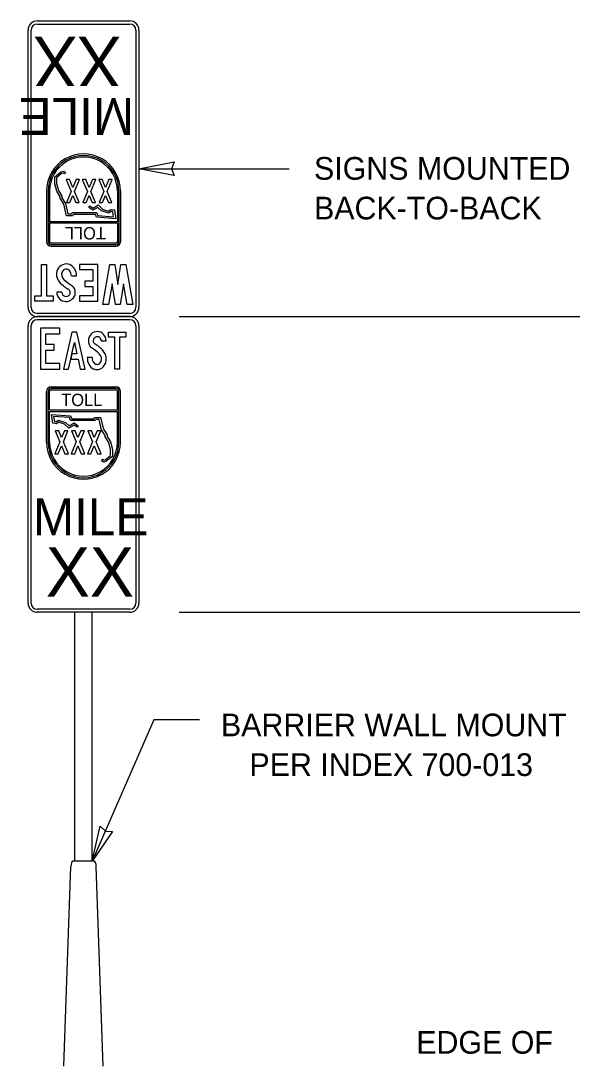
# Model space of a CAD drawing. Extents: x 57428 to 58066, y 11696 to 12105.
# Drawn here: x 57752.3 to 57820.2, y 11796.7 to 11925.7 of the extents above; entities that cross this region are included whole.
import ezdxf

# ---------------------------------------------------------------- set-up
doc = ezdxf.new("R2010")
doc.units = 0
for name, color, linetype in [('DimLines_dp', 7, 'Continuous'), ('NonPlottingEle_dp', 7, 'Continuous'), ('SignPanel', 7, 'Continuous'), ('XSGrdLine_ex', 7, 'Continuous')]:
    doc.layers.add(name, color=color, linetype=linetype)

msp = doc.modelspace()

# ---------------------------------------------------------------- linework, layer by layer
at = {"layer": 'DimLines_dp'}
for p, q in [((57766.83, 11907.47), (57771.18, 11908.31)), ((57771.18, 11908.31), (57770.85, 11907.47)), ((57766.83, 11907.47), (57785.36, 11907.47)), ((57771.18, 11906.66), (57766.83, 11907.47)), ((57770.85, 11907.47), (57771.18, 11906.66)), ((57919.19, 11889.21), (57771.8, 11889.21)), ((57919.19, 11852.71), (57771.8, 11852.71)), ((57768.66, 11839.46), (57761.07, 11822.02)), ((57774.31, 11839.46), (57768.66, 11839.46)), ((57761.07, 11822.02), (57762.04, 11826.34)), ((57763.55, 11825.68), (57761.07, 11822.02)), ((57762.04, 11826.34), (57762.68, 11825.7)), ((57762.68, 11825.7), (57763.55, 11825.68))]:
    msp.add_line(p, q, dxfattribs=at)
at = {"layer": 'NonPlottingEle_dp'}
for p, q in [((57758.91, 11822.02), (57758.91, 11852.73)), ((57761.07, 11822.02), (57761.07, 11852.73))]:
    msp.add_line(p, q, dxfattribs=at)
at = {"layer": 'SignPanel'}
for p, q in [((57756.43, 11906.48), (57757.18, 11907.09)), ((57757.29, 11906.88), (57756.66, 11906.37)), ((57757.18, 11907.09), (57757.54, 11907.18)), ((57757.49, 11906.93), (57757.29, 11906.88)), ((57757.63, 11906.83), (57757.49, 11906.93)), ((57757.54, 11907.18), (57757.77, 11907.02)), ((57757.77, 11907.02), (57757.63, 11906.83)), ((57756.43, 11905.62), (57756.43, 11906.48)), ((57756.68, 11904.69), (57756.43, 11905.62)), ((57756.66, 11906.37), (57756.66, 11905.65)), ((57756.66, 11905.65), (57756.9, 11904.78)), ((57755.43, 11904.74), (57755.43, 11898.46)), ((57755.62, 11904.74), (57755.62, 11898.46)), ((57755.81, 11904.74), (57755.81, 11900.94)), ((57757.09, 11904.02), (57756.68, 11904.69)), ((57756.9, 11904.78), (57757.32, 11904.08)), ((57764.17, 11904.74), (57764.17, 11900.94)), ((57764.36, 11904.74), (57764.36, 11898.46)), ((57764.55, 11904.74), (57764.55, 11898.46)), ((57757.09, 11903.83), (57757.09, 11904.02)), ((57757.54, 11903.11), (57757.09, 11903.83)), ((57757.32, 11904.08), (57757.32, 11903.9)), ((57757.32, 11903.9), (57757.76, 11903.2)), ((57757.88, 11901.68), (57757.54, 11903.11)), ((57757.76, 11903.2), (57758.06, 11901.91)), ((57761.16, 11902.62), (57761.79, 11903)), ((57761.79, 11903), (57762.33, 11902.5)), ((57758.61, 11901.68), (57757.88, 11901.68)), ((57758.06, 11901.91), (57758.49, 11901.91)), ((57758.49, 11901.91), (57758.59, 11902.06)), ((57758.59, 11902.06), (57761.6, 11902.06)), ((57758.71, 11901.83), (57758.61, 11901.68)), ((57761.45, 11901.83), (57758.71, 11901.83)), ((57760.65, 11902.69), (57760.78, 11902.88)), ((57761.15, 11902.35), (57760.65, 11902.69)), ((57760.78, 11902.88), (57761.16, 11902.62)), ((57761.76, 11902.71), (57761.15, 11902.35)), ((57761.58, 11901.49), (57761.45, 11901.83)), ((57761.6, 11902.06), (57761.74, 11901.7)), ((57761.74, 11901.7), (57763.69, 11901.55)), ((57762.21, 11902.29), (57761.76, 11902.71)), ((57763.13, 11902), (57762.21, 11902.29)), ((57762.33, 11902.5), (57763.08, 11902.25)), ((57762.7, 11901.64), (57762.7, 11901.64)), ((57763.08, 11902.25), (57763.33, 11902.45)), ((57763.4, 11902.21), (57763.13, 11902)), ((57763.33, 11902.45), (57763.79, 11902.39)), ((57763.59, 11902.18), (57763.4, 11902.21)), ((57763.69, 11901.55), (57763.59, 11902.18)), ((57763.79, 11902.39), (57763.96, 11901.3)), ((57764.17, 11900.94), (57755.81, 11900.94)), ((57755.81, 11900.74), (57755.81, 11898.46)), ((57764.17, 11900.74), (57755.81, 11900.74)), ((57763.96, 11901.3), (57761.58, 11901.49)), ((57764.17, 11900.74), (57764.17, 11898.46)), ((57763.98, 11898.28), (57756, 11898.28)), ((57763.98, 11898.08), (57756, 11898.08)), ((57763.98, 11897.89), (57756, 11897.89)), ((57758.49, 11894.24), (57759.12, 11894.24)), ((57758.49, 11894.24), (57759.12, 11894.24)), ((57758.49, 11894.24), (57759.12, 11894.24)), ((57757.3, 11892.23), (57756.68, 11892.23)), ((57757.3, 11892.23), (57756.68, 11892.23)), ((57757.3, 11892.23), (57756.68, 11892.23)), ((57762.18, 11886.22), (57762.77, 11886.22)), ((57762.18, 11886.22), (57762.77, 11886.22)), ((57762.18, 11886.22), (57762.77, 11886.22)), ((57761.05, 11884.18), (57760.45, 11884.18)), ((57761.05, 11884.18), (57760.45, 11884.18)), ((57761.05, 11884.18), (57760.45, 11884.18)), ((57755.43, 11873.71), (57755.43, 11879.99)), ((57755.62, 11873.71), (57755.62, 11879.99)), ((57755.81, 11877.71), (57755.81, 11879.99)), ((57756, 11880.56), (57763.98, 11880.56)), ((57756, 11880.37), (57763.98, 11880.37)), ((57756, 11880.17), (57763.98, 11880.17)), ((57764.17, 11877.71), (57764.17, 11879.99)), ((57764.36, 11873.71), (57764.36, 11879.99)), ((57764.55, 11873.71), (57764.55, 11879.99)), ((57755.81, 11877.71), (57764.17, 11877.71)), ((57755.81, 11873.71), (57755.81, 11877.52)), ((57755.81, 11877.52), (57764.17, 11877.52)), ((57756.19, 11876.06), (57756.02, 11877.15)), ((57756.02, 11877.15), (57758.4, 11876.96)), ((57764.17, 11873.71), (57764.17, 11877.52)), ((57756.65, 11876), (57756.19, 11876.06)), ((57758.24, 11876.75), (57756.29, 11876.9)), ((57756.29, 11876.9), (57756.39, 11876.27)), ((57756.39, 11876.27), (57756.58, 11876.24)), ((57756.58, 11876.24), (57756.85, 11876.46)), ((57756.9, 11876.2), (57756.65, 11876)), ((57756.85, 11876.46), (57757.77, 11876.16)), ((57757.65, 11875.95), (57756.9, 11876.2)), ((57757.28, 11876.81), (57757.28, 11876.81)), ((57758.19, 11875.45), (57757.65, 11875.95)), ((57757.77, 11876.16), (57758.22, 11875.74)), ((57758.82, 11875.83), (57758.19, 11875.45)), ((57758.22, 11875.74), (57758.83, 11876.1)), ((57758.38, 11876.39), (57758.24, 11876.75)), ((57761.39, 11876.39), (57758.38, 11876.39)), ((57758.4, 11876.96), (57758.54, 11876.62)), ((57758.54, 11876.62), (57761.27, 11876.62)), ((57759.2, 11875.57), (57758.82, 11875.83)), ((57758.83, 11876.1), (57759.33, 11875.76)), ((57761.27, 11876.62), (57761.37, 11876.77)), ((57761.37, 11876.77), (57762.1, 11876.77)), ((57761.49, 11876.54), (57761.39, 11876.39)), ((57761.92, 11876.54), (57761.49, 11876.54)), ((57762.22, 11875.25), (57761.92, 11876.54)), ((57762.1, 11876.77), (57762.44, 11875.34)), ((57759.33, 11875.76), (57759.2, 11875.57)), ((57762.66, 11874.55), (57762.22, 11875.25)), ((57762.44, 11875.34), (57762.89, 11874.62)), ((57762.66, 11874.37), (57762.66, 11874.55)), ((57762.89, 11874.62), (57762.89, 11874.43)), ((57763.09, 11873.67), (57762.66, 11874.37)), ((57762.89, 11874.43), (57763.3, 11873.76)), ((57763.32, 11872.8), (57763.09, 11873.67)), ((57763.3, 11873.76), (57763.55, 11872.84)), ((57762.69, 11871.57), (57763.32, 11872.08)), ((57763.55, 11871.97), (57762.8, 11871.36)), ((57763.32, 11872.08), (57763.32, 11872.8)), ((57763.55, 11872.84), (57763.55, 11871.97)), ((57762.22, 11871.43), (57762.35, 11871.62)), ((57762.44, 11871.27), (57762.22, 11871.43)), ((57762.35, 11871.62), (57762.49, 11871.52)), ((57762.8, 11871.36), (57762.44, 11871.27)), ((57762.49, 11871.52), (57762.69, 11871.57))]:
    msp.add_line(p, q, dxfattribs=at)
for points in [[(57754.29, 11925.72), (57765.69, 11925.72)], [(57754.29, 11925.34), (57765.69, 11925.34)], [(57753.15, 11890.37), (57753.15, 11924.58)], [(57753.53, 11890.37), (57753.53, 11924.58)], [(57766.45, 11924.58), (57766.45, 11890.37)], [(57766.83, 11924.58), (57766.83, 11890.37)], [(57765.69, 11889.61), (57754.29, 11889.61)], [(57765.69, 11889.23), (57754.29, 11889.23)], [(57754.29, 11889.23), (57765.69, 11889.23)], [(57754.29, 11888.85), (57765.69, 11888.85)], [(57753.15, 11853.87), (57753.15, 11888.08)], [(57753.53, 11853.87), (57753.53, 11888.08)], [(57766.45, 11888.08), (57766.45, 11853.87)], [(57766.83, 11888.08), (57766.83, 11853.87)], [(57765.69, 11853.11), (57754.29, 11853.11)], [(57765.69, 11852.73), (57754.29, 11852.73)]]:
    msp.add_lwpolyline(points, dxfattribs=at)
for points in [[(57759.07, 11906.16), (57758.66, 11905.18), (57758.25, 11906.16), (57757.83, 11906.16), (57758.45, 11904.67), (57757.88, 11903.31), (57758.3, 11903.31), (57758.66, 11904.16), (57759.02, 11903.31), (57759.45, 11903.31), (57758.87, 11904.67), (57759.5, 11906.16)], [(57761.09, 11906.16), (57760.68, 11905.18), (57760.27, 11906.16), (57759.84, 11906.16), (57760.46, 11904.67), (57759.89, 11903.31), (57760.32, 11903.31), (57760.68, 11904.16), (57761.04, 11903.31), (57761.46, 11903.31), (57760.89, 11904.67), (57761.51, 11906.16)], [(57763.1, 11906.16), (57762.69, 11905.18), (57762.28, 11906.16), (57761.86, 11906.16), (57762.48, 11904.67), (57761.91, 11903.31), (57762.33, 11903.31), (57762.69, 11904.16), (57763.05, 11903.31), (57763.48, 11903.31), (57762.91, 11904.67), (57763.53, 11906.16)], [(57755.44, 11891.78), (57756.26, 11891.78), (57756.26, 11891.15), (57753.99, 11891.15), (57753.99, 11891.78), (57754.82, 11891.78), (57754.82, 11895.65), (57755.44, 11895.65)], [(57755.44, 11891.78), (57756.26, 11891.78), (57756.26, 11891.15), (57753.99, 11891.15), (57753.99, 11891.78), (57754.82, 11891.78), (57754.82, 11895.65), (57755.44, 11895.65)], [(57755.44, 11891.78), (57756.26, 11891.78), (57756.26, 11891.15), (57753.99, 11891.15), (57753.99, 11891.78), (57754.82, 11891.78), (57754.82, 11895.65), (57755.44, 11895.65)], [(57761.14, 11895.02), (57761.14, 11893.58), (57760.17, 11893.58), (57760.17, 11892.95), (57761.14, 11892.95), (57761.14, 11891.78), (57759.5, 11891.78), (57759.5, 11891.15), (57761.76, 11891.15), (57761.76, 11895.65), (57759.5, 11895.65), (57759.5, 11895.02)], [(57761.14, 11895.02), (57761.14, 11893.58), (57760.17, 11893.58), (57760.17, 11892.95), (57761.14, 11892.95), (57761.14, 11891.78), (57759.5, 11891.78), (57759.5, 11891.15), (57761.76, 11891.15), (57761.76, 11895.65), (57759.5, 11895.65), (57759.5, 11895.02)], [(57761.14, 11895.02), (57761.14, 11893.58), (57760.17, 11893.58), (57760.17, 11892.95), (57761.14, 11892.95), (57761.14, 11891.78), (57759.5, 11891.78), (57759.5, 11891.15), (57761.76, 11891.15), (57761.76, 11895.65), (57759.5, 11895.65), (57759.5, 11895.02)], [(57764.93, 11893.26), (57764.52, 11890.7), (57763.92, 11890.7), (57763.51, 11893.26), (57763.06, 11890.7), (57762.37, 11890.7), (57763.24, 11895.65), (57763.83, 11895.65), (57764.22, 11893.18), (57764.61, 11895.65), (57765.2, 11895.65), (57766.07, 11890.7), (57765.38, 11890.7)], [(57764.93, 11893.26), (57764.52, 11890.7), (57763.92, 11890.7), (57763.51, 11893.26), (57763.06, 11890.7), (57762.37, 11890.7), (57763.24, 11895.65), (57763.83, 11895.65), (57764.22, 11893.18), (57764.61, 11895.65), (57765.2, 11895.65), (57766.07, 11890.7), (57765.38, 11890.7)], [(57764.93, 11893.26), (57764.52, 11890.7), (57763.92, 11890.7), (57763.51, 11893.26), (57763.06, 11890.7), (57762.37, 11890.7), (57763.24, 11895.65), (57763.83, 11895.65), (57764.22, 11893.18), (57764.61, 11895.65), (57765.2, 11895.65), (57766.07, 11890.7), (57765.38, 11890.7)], [(57755.35, 11883.45), (57755.35, 11885.07), (57756.37, 11885.07), (57756.37, 11885.78), (57755.35, 11885.78), (57755.35, 11887.1), (57757.07, 11887.1), (57757.07, 11887.81), (57754.7, 11887.81), (57754.7, 11882.74), (57757.07, 11882.74), (57757.07, 11883.45)], [(57755.35, 11883.45), (57755.35, 11885.07), (57756.37, 11885.07), (57756.37, 11885.78), (57755.35, 11885.78), (57755.35, 11887.1), (57757.07, 11887.1), (57757.07, 11887.81), (57754.7, 11887.81), (57754.7, 11882.74), (57757.07, 11882.74), (57757.07, 11883.45)], [(57755.35, 11883.45), (57755.35, 11885.07), (57756.37, 11885.07), (57756.37, 11885.78), (57755.35, 11885.78), (57755.35, 11887.1), (57757.07, 11887.1), (57757.07, 11887.81), (57754.7, 11887.81), (57754.7, 11882.74), (57757.07, 11882.74), (57757.07, 11883.45)], [(57759.32, 11883.97), (57759.59, 11882.74), (57760.2, 11882.74), (57759.18, 11887.32), (57758.55, 11887.32), (57757.53, 11882.74), (57758.13, 11882.74), (57758.41, 11883.97)], [(57758.55, 11884.61), (57758.41, 11883.97), (57759.32, 11883.97), (57759.59, 11882.74), (57760.2, 11882.74), (57759.18, 11887.32), (57758.55, 11887.32), (57757.53, 11882.74), (57758.13, 11882.74), (57758.86, 11886.02), (57759.18, 11884.61)], [(57758.55, 11884.61), (57758.41, 11883.97), (57759.32, 11883.97), (57759.59, 11882.74), (57760.2, 11882.74), (57759.18, 11887.32), (57758.55, 11887.32), (57757.53, 11882.74), (57758.13, 11882.74), (57758.86, 11886.02), (57759.18, 11884.61)], [(57763.83, 11886.68), (57763.05, 11886.68), (57763.05, 11887.32), (57765.2, 11887.32), (57765.2, 11886.68), (57764.42, 11886.68), (57764.42, 11882.74), (57763.83, 11882.74)], [(57763.83, 11886.68), (57763.05, 11886.68), (57763.05, 11887.32), (57765.2, 11887.32), (57765.2, 11886.68), (57764.42, 11886.68), (57764.42, 11882.74), (57763.83, 11882.74)], [(57763.83, 11886.68), (57763.05, 11886.68), (57763.05, 11887.32), (57765.2, 11887.32), (57765.2, 11886.68), (57764.42, 11886.68), (57764.42, 11882.74), (57763.83, 11882.74)], [(57758.86, 11886.02), (57759.18, 11884.61), (57758.55, 11884.61)], [(57756.88, 11872.29), (57757.29, 11873.27), (57757.7, 11872.29), (57758.12, 11872.29), (57757.5, 11873.78), (57758.07, 11875.14), (57757.65, 11875.14), (57757.29, 11874.29), (57756.93, 11875.14), (57756.5, 11875.14), (57757.07, 11873.78), (57756.45, 11872.29)], [(57758.9, 11872.29), (57759.3, 11873.27), (57759.71, 11872.29), (57760.14, 11872.29), (57759.52, 11873.78), (57760.09, 11875.14), (57759.66, 11875.14), (57759.3, 11874.29), (57758.95, 11875.14), (57758.52, 11875.14), (57759.09, 11873.78), (57758.47, 11872.29)], [(57760.91, 11872.29), (57761.32, 11873.27), (57761.73, 11872.29), (57762.16, 11872.29), (57761.53, 11873.78), (57762.11, 11875.14), (57761.68, 11875.14), (57761.32, 11874.29), (57760.96, 11875.14), (57760.53, 11875.14), (57761.11, 11873.78), (57760.48, 11872.29)]]:
    msp.add_lwpolyline(points, close=True, dxfattribs=at)
for centre, radius, start, end in [((57754.29, 11924.58), 1.14, 90, 180), ((57754.29, 11924.58), 0.76, 90, 180), ((57765.69, 11924.58), 1.14, 360, 90), ((57765.69, 11924.58), 0.76, 360, 90), ((57754.29, 11890.37), 1.14, 180, 270), ((57754.29, 11890.37), 0.76, 180, 270), ((57765.69, 11890.37), 1.14, 270, 360), ((57765.69, 11890.37), 0.76, 270, 360), ((57754.29, 11888.08), 1.14, 90, 180), ((57754.29, 11888.08), 0.76, 90, 180), ((57765.69, 11888.08), 1.14, 0, 90), ((57765.69, 11888.08), 0.76, 0, 90), ((57754.29, 11853.87), 1.14, 180, 270), ((57754.29, 11853.87), 0.76, 180, 270), ((57765.69, 11853.87), 1.14, 270, 360), ((57765.69, 11853.87), 0.76, 270, 360)]:
    msp.add_arc(centre, radius, start, end, dxfattribs=at)
for centre, major_axis, ratio, start_param, end_param in [((57759.99, 11904.74), (0, 4.56), 0.9997, 4.712389, 7.853982), ((57759.99, 11904.74), (0, 4.37), 0.9997, 4.712389, 7.853982), ((57759.99, 11904.74), (0, 4.18), 0.9997, 4.712389, 7.853982), ((57756, 11898.47), (0, -0.57), 0.9997, 4.712389, 6.283185), ((57756, 11898.47), (0, -0.38), 0.9997, 4.712389, 6.283185), ((57756, 11898.47), (0, -0.19), 0.9997, 4.712389, 6.283185), ((57763.98, 11898.47), (0, -0.38), 0.9997, 0, 1.570796), ((57763.98, 11898.47), (0, -0.19), 0.9997, 0, 1.570796), ((57763.98, 11898.47), (0, -0.57), 0.9997, 0, 1.570796), ((57757.87, 11894.49), (0, -1.23), 0.981197, 2.786047, 4.251692), ((57757.87, 11894.49), (0, -1.23), 0.981197, 2.786047, 4.251692), ((57757.87, 11894.49), (0, -1.23), 0.981197, 2.786047, 4.251692), ((57757.67, 11894.31), (0, -1.47), 0.981197, 1.526364, 2.701682), ((57757.67, 11894.31), (0, -1.47), 0.981197, 1.526364, 2.701682), ((57757.67, 11894.31), (0, -1.47), 0.981197, 1.526364, 2.701682), ((57758.03, 11894.43), (0, -1.4), 0.981197, 4.260987, 5.485755), ((57758.03, 11894.43), (0, -1.4), 0.981197, 4.260987, 5.485755), ((57758.03, 11894.43), (0, -1.4), 0.981197, 4.260987, 5.485755), ((57758.04, 11894.42), (0, -0.78), 0.981197, 4.254409, 5.632398), ((57758.04, 11894.42), (0, -0.78), 0.981197, 4.254409, 5.632398), ((57758.04, 11894.42), (0, -0.78), 0.981197, 4.254409, 5.632398), ((57757.85, 11894.5), (0, -0.572), 0.981197, 2.261787, 4.23006), ((57757.85, 11894.5), (0, -0.572), 0.981197, 2.261787, 4.23006), ((57757.85, 11894.5), (0, -0.572), 0.981197, 2.261787, 4.23006), ((57757.61, 11894.28), (0, -0.897), 0.981197, 1.524757, 2.28214), ((57757.61, 11894.28), (0, -0.897), 0.981197, 1.524757, 2.28214), ((57757.61, 11894.28), (0, -0.897), 0.981197, 1.524757, 2.28214), ((57760.15, 11896.4), (0, -4.32), 0.981197, 5.462886, 5.782242), ((57760.15, 11896.4), (0, -4.32), 0.981197, 5.462886, 5.782242), ((57760.15, 11896.4), (0, -4.32), 0.981197, 5.462886, 5.782242), ((57760.68, 11897.09), (0, -4.56), 0.981197, 5.515137, 5.786988), ((57760.68, 11897.09), (0, -4.56), 0.981197, 5.515137, 5.786988), ((57760.68, 11897.09), (0, -4.56), 0.981197, 5.515137, 5.786988), ((57757.9, 11892.21), (0, -0.453), 0.981197, 0.87378, 2.656959), ((57757.9, 11892.21), (0, -0.453), 0.981197, 0.87378, 2.656959), ((57757.9, 11892.21), (0, -0.453), 0.981197, 0.87378, 2.656959), ((57757.94, 11892.23), (0, -1.05), 0.981197, 1.534831, 2.511766), ((57757.94, 11892.23), (0, -1.05), 0.981197, 1.534831, 2.511766), ((57757.94, 11892.23), (0, -1.05), 0.981197, 1.534831, 2.511766), ((57757.83, 11892.26), (0, -1.17), 0.981197, 4.736267, 7.790596), ((57757.83, 11892.26), (0, -1.17), 0.981197, 4.736267, 7.790596), ((57757.83, 11892.26), (0, -1.17), 0.981197, 4.736267, 7.790596), ((57757.84, 11892.27), (0, -0.55), 0.981197, 4.786904, 7.140738), ((57757.84, 11892.27), (0, -0.55), 0.981197, 4.786904, 7.140738), ((57757.84, 11892.27), (0, -0.55), 0.981197, 4.786904, 7.140738), ((57761.57, 11886.23), (0, 1.07), 0.91923, 1.534831, 2.511766), ((57761.57, 11886.23), (0, 1.07), 0.91923, 1.534831, 2.511766), ((57761.57, 11886.23), (0, 1.07), 0.91923, 1.534831, 2.511766), ((57761.68, 11886.19), (0, 1.19), 0.91923, 4.736267, 7.790596), ((57761.68, 11886.19), (0, 1.19), 0.91923, 4.736267, 7.790596), ((57761.68, 11886.19), (0, 1.19), 0.91923, 4.736267, 7.790596), ((57761.61, 11886.25), (0, 0.46), 0.91923, 0.87378, 2.656959), ((57761.61, 11886.25), (0, 0.46), 0.91923, 0.87378, 2.656959), ((57761.61, 11886.25), (0, 0.46), 0.91923, 0.87378, 2.656959), ((57761.67, 11886.18), (0, 0.558), 0.91923, 4.786904, 7.140738), ((57761.67, 11886.18), (0, 0.558), 0.91923, 4.786904, 7.140738), ((57761.67, 11886.18), (0, 0.558), 0.91923, 4.786904, 7.140738), ((57758.96, 11881.29), (0, 4.63), 0.91923, 5.515137, 5.786988), ((57758.96, 11881.29), (0, 4.63), 0.91923, 5.515137, 5.786988), ((57758.96, 11881.29), (0, 4.63), 0.91923, 5.515137, 5.786988), ((57759.47, 11881.99), (0, 4.39), 0.91923, 5.462886, 5.782242), ((57759.47, 11881.99), (0, 4.39), 0.91923, 5.462886, 5.782242), ((57759.47, 11881.99), (0, 4.39), 0.91923, 5.462886, 5.782242), ((57761.49, 11883.99), (0, 1.42), 0.91923, 4.260987, 5.485755), ((57761.49, 11883.99), (0, 1.42), 0.91923, 4.260987, 5.485755), ((57761.49, 11883.99), (0, 1.42), 0.91923, 4.260987, 5.485755), ((57761.83, 11884.11), (0, 1.5), 0.91923, 1.526364, 2.701682), ((57761.83, 11884.11), (0, 1.5), 0.91923, 1.526364, 2.701682), ((57761.83, 11884.11), (0, 1.5), 0.91923, 1.526364, 2.701682), ((57761.88, 11884.14), (0, 0.911), 0.91923, 1.524757, 2.28214), ((57761.88, 11884.14), (0, 0.911), 0.91923, 1.524757, 2.28214), ((57761.88, 11884.14), (0, 0.911), 0.91923, 1.524757, 2.28214), ((57761.66, 11883.91), (0, 0.581), 0.91923, 2.261787, 4.23006), ((57761.66, 11883.91), (0, 0.581), 0.91923, 2.261787, 4.23006), ((57761.66, 11883.91), (0, 0.581), 0.91923, 2.261787, 4.23006), ((57761.48, 11883.99), (0, 0.792), 0.91923, 4.254409, 5.632398), ((57761.48, 11883.99), (0, 0.792), 0.91923, 4.254409, 5.632398), ((57761.48, 11883.99), (0, 0.792), 0.91923, 4.254409, 5.632398), ((57761.64, 11883.93), (0, 1.24), 0.91923, 2.786047, 4.251692), ((57761.64, 11883.93), (0, 1.24), 0.91923, 2.786047, 4.251692), ((57761.64, 11883.93), (0, 1.24), 0.91923, 2.786047, 4.251692), ((57756, 11879.99), (0, 0.57), 0.9997, 0, 1.570796), ((57756, 11879.99), (0, 0.38), 0.9997, 0, 1.570796), ((57756, 11879.99), (0, 0.19), 0.9997, 0, 1.570796), ((57763.98, 11879.99), (0, 0.57), 0.9997, 4.712389, 6.283185), ((57763.98, 11879.99), (0, 0.38), 0.9997, 4.712389, 6.283185), ((57763.98, 11879.99), (0, 0.19), 0.9997, 4.712389, 6.283185), ((57759.99, 11873.71), (0, -4.56), 0.9997, 4.712389, 7.853982), ((57759.99, 11873.71), (0, -4.37), 0.9997, 4.712389, 7.853982), ((57759.99, 11873.71), (0, -4.18), 0.9997, 4.712389, 7.853982)]:
    msp.add_ellipse(centre, major_axis=major_axis, ratio=ratio, start_param=start_param, end_param=end_param, dxfattribs=at)
at = {"layer": 'XSGrdLine_ex'}
for p, q in [((57761.3, 11822.02), (57758.68, 11822.02)), ((57757.56, 11796.71), (57758.43, 11821.33)), ((57762.42, 11796.71), (57761.56, 11821.33))]:
    msp.add_line(p, q, dxfattribs=at)
for centre, start_param, end_param in [((57758.68, 11821.25), 0, 1.465919), ((57761.3, 11821.25), 4.817266, 6.283185)]:
    msp.add_ellipse(centre, major_axis=(0, 0.77), ratio=0.333333, start_param=start_param, end_param=end_param, dxfattribs=at)

# ---------------------------------------------------------------- texts
at = {"layer": 'DimLines_dp'}
for s, p in [('SIGNS MOUNTED', (57788.42, 11906.12)), ('BACK-TO-BACK', (57788.42, 11901.22)), ('BARRIER WALL MOUNT', (57776.94, 11837.42)), ('PER INDEX 700-013', (57780.46, 11832.52)), ('EDGE OF ', (57801.03, 11798.24))]:
    msp.add_text(s, height=2.8, dxfattribs=at).set_placement(p)
at = {"layer": 'SignPanel'}
for s, height, p in [('XX', 6.083, (57764.63, 11923.79)), ('MILE', 4.562, (57766.24, 11916.22)), ('TOLL', 1.519, (57762.75, 11900.27))]:
    msp.add_text(s, height=height, rotation=180, dxfattribs=at).set_placement(p)
for s, height, p in [('TOLL', 1.519, (57757.23, 11878.18)), ('MILE', 4.562, (57753.74, 11862.23)), ('XX', 6.083, (57755.35, 11854.66))]:
    msp.add_text(s, height=height, dxfattribs=at).set_placement(p)

doc.saveas('drawing.dxf')
